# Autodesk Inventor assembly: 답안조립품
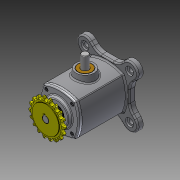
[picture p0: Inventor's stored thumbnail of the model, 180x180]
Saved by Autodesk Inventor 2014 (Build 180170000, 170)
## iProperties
Created: 2016-05
Part Number: 답안조립품
Document SubType Name: Assembly
Designer: Administrator
Author: Administrator
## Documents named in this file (11)
- C:\Users\Administrator\Desktop\460507V1014\답안조립품.iam
- C:\Users\Administrator\Desktop\460507V1014\본체.ipt
- C:\Users\Administrator\Desktop\460507V1014\M4x0.7x12.ipt
- C:\Users\Administrator\Desktop\460507V1014\베어링-6203.ipt
- C:\Users\Administrator\Desktop\460507V1014\부시.ipt
- C:\Users\Administrator\Desktop\460507V1014\스프로킷.ipt
- C:\Users\Administrator\Desktop\460507V1014\슬라이더.ipt
- C:\Users\Administrator\Desktop\460507V1014\오일실.ipt
- C:\Users\Administrator\Desktop\460507V1014\커버.ipt
- C:\Users\Administrator\Desktop\460507V1014\키5x5.ipt
- C:\Users\Administrator\Desktop\460507V1014\편심축.ipt
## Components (8 placed, 1 different names)
1. M4x0.7x12:1
2. M4x0.7x12:3
3. M4x0.7x12:4
4. M4x0.7x12:5
5. M4x0.7x12:2
6. M4x0.7x12:6
7. M4x0.7x12:7
8. M4x0.7x12:8
